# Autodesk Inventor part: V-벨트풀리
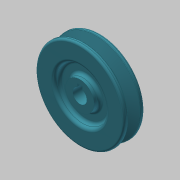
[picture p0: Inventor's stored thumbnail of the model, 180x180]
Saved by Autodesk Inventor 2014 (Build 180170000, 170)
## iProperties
Created: 2019-09
Part Number: V-벨트풀리
Material: 알루미늄 6061
Document SubType Name: Modeling
Designer: mduedu
Density: 2.71 g/cm^3
Appearance: 커뎃 파란색
Mass: 202.902 g
Surface Area: 230.066 cm^2
Volume: 74.8717 cm^3
Author: mduedu
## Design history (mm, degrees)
sketch "스케치1"
  geometry: L1 (-10, 0)-(10, 0); L2 (10, 0)-(10, 43.5); L3 (10, 43.5)-(-10, 43.5); L4 (-10, 43.5)-(-10, 0); L5 (0, 0)-(0, 43.5); L6 (-5.976, 43.5)-(-2.154, 31); L7 (-2.154, 31)-(2.154, 31); L8 (2.154, 31)-(5.976, 43.5); L9 (-10, 39)-(10, 39); 3 further points
  constraints: 18 end point, 8 point on line, 3 perpendicular, 2 midpoint, 2 parallel, 1 coincident, 1 horizontal, 1 other
  dimensions: "d0" = 87 diameter of L3 L1; "d3" = 12.5 distance between parallel lines of L7 L3; "d4" = 34 deg angle of L8 L6; "d5" = 20 distance between parallel lines of L2 L4; "d6" = 8 distance between parallel lines of L9 L7; "d7" = 9.2 distance of point (4.6, 39) point (-4.6, 39)
revolve "회전1" sketch "스케치1" stored, may be unused: angle "d8" = 90 deg
sketch "스케치2"
  geometry: C1 r 14 at (0, 0); C2 r 25 at (0, 0); 1 further point
  constraints: 2 centre point, 2 coincident
  dimensions: "d9" = 28 diameter of C1; "d10" = 50 diameter of C2
extrude "돌출1" cut sketch "스케치2" distance "d11" = 6; taper "d12" = 0 deg
fillet "모깎기1" dims "d13" = 3
fillet "모깎기2" dims "d14" = 3
fillet "모깎기3" dims "d15" = 0.5, "d16" = 1, "d17" = 2
sketch "스케치3"
  geometry: L1 (-2.5, 6.538)-(2.5, 6.538); L2 (2.5, 6.538)-(2.5, 9.3); L3 (2.5, 9.3)-(-2.5, 9.3); L4 (-2.5, 9.3)-(-2.5, 6.538); A1 r 7 centre (0, 0) between (-2.5, 6.538) and (2.5, 6.538); 1 further point
  constraints: 8 end point, 2 parallel, 2 point on circle, 1 centre point, 1 coincident, 1 horizontal, 1 perpendicular
  dimensions: "d18" = 14 diameter of A1; "d20" = 5 distance of L2.end L3.end; "d21" = 16.3 dimension on A1 L3
extrude "돌출2" cut sketch "스케치3" stored distance "d22" = 6; taper "d23" = 0 deg
node "솔리드1"
mirror "대칭1"
